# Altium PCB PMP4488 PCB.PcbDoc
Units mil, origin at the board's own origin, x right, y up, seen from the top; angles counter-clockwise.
Board outline 1702.94 x 773.81 mil, 2 copper layers (Top Layer, Bottom Layer), stack 62 mil thick; 34 components, 20 nets, 140 pads, 96 vias.
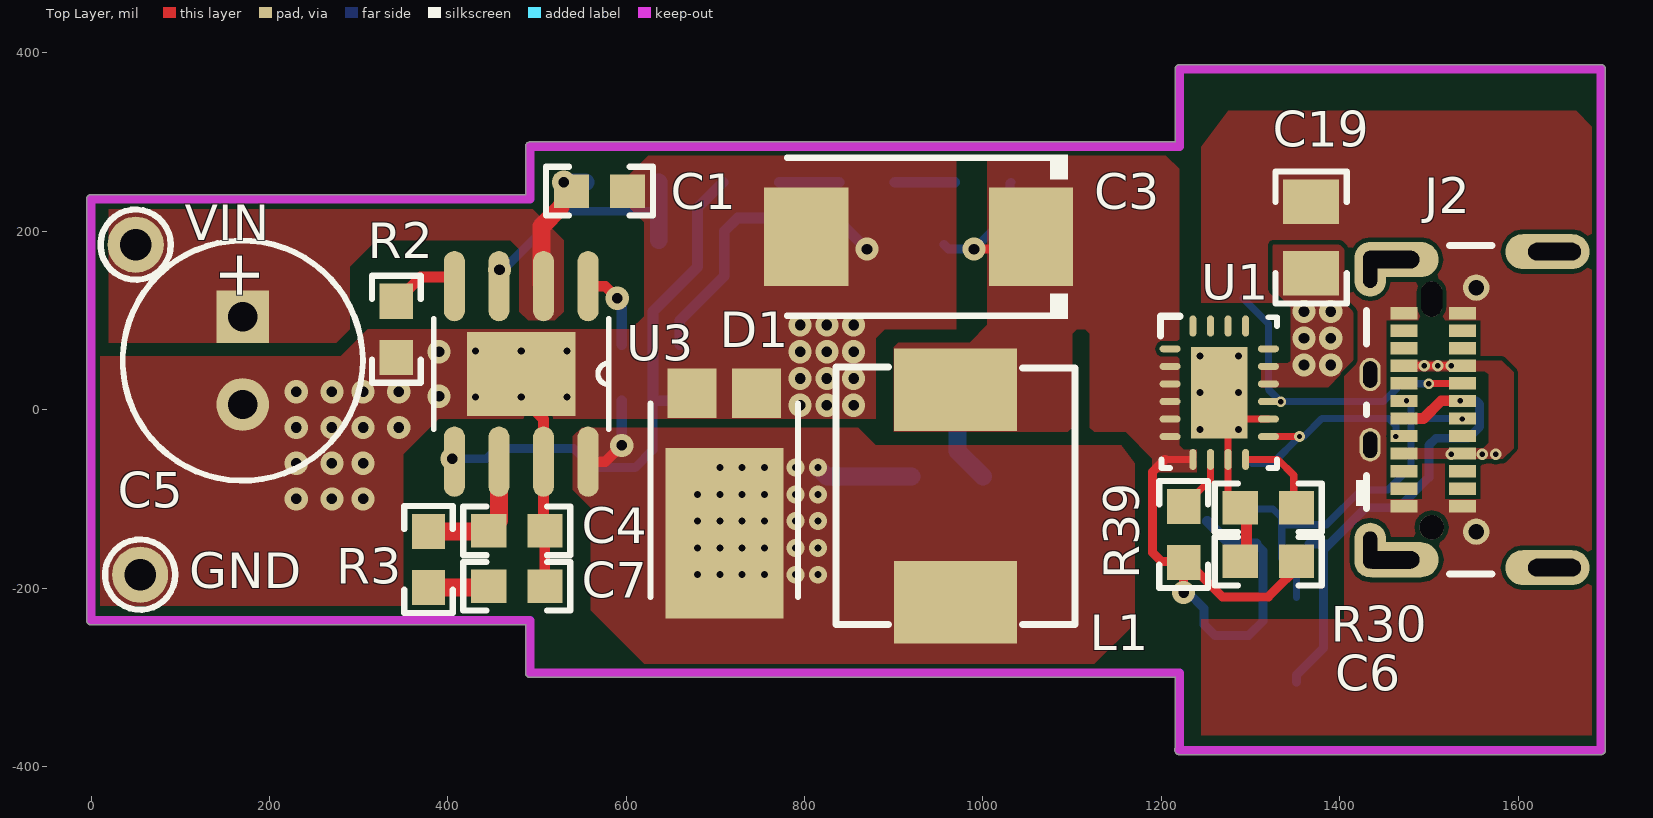
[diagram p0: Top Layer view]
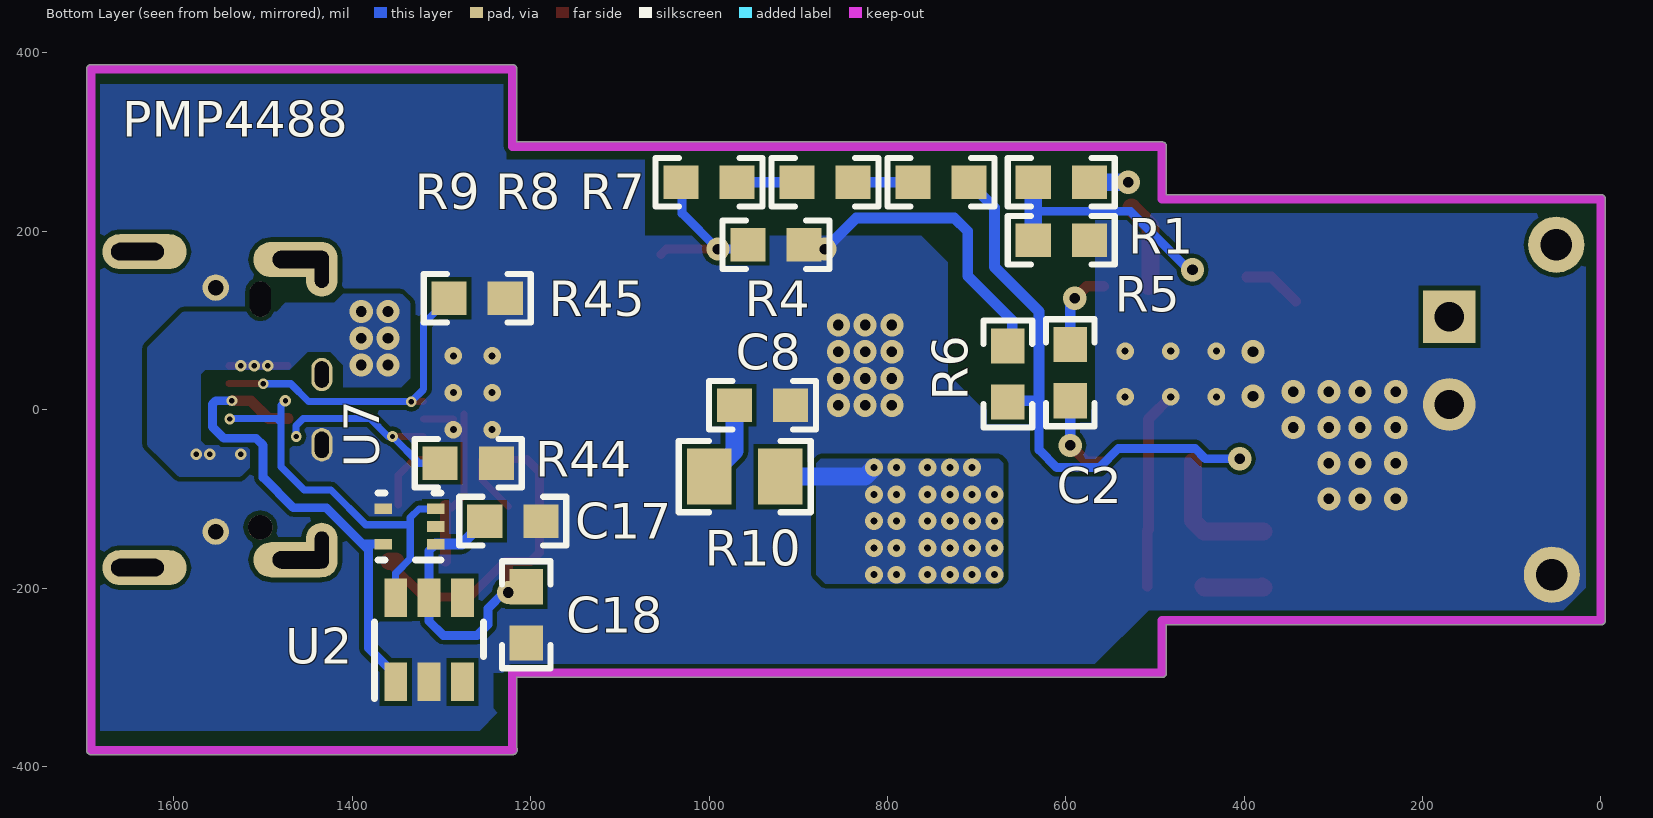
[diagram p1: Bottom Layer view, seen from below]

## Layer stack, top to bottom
Top Layer: signal copper 1.4
Dielectric: core 59.2, FR-4, Dk 4.8
Bottom Layer: signal copper 1.4

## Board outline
487.11,-295.28 487.11,-241.24 0,-241.24 cw(c0,-236.22) -5.01,-236.22 -5.01,236.22 cw(c0,236.22) 0,241.24 487.11,241.24 487.11,295.28 cw(c492.13,295.28) 492.13,300.29 1215.46,300.29 1215.46,381.89 cw(c1220.47,381.89) 1220.47,386.9 1692.91,386.9 cw(c1692.91,381.89) 1697.93,381.89 1697.93,-381.89 cw(c1692.91,-381.89) 1692.91,-386.9 1220.47,-386.9 cw(c1220.47,-381.89) 1216.91,-385.42 1216.93,-385.44 1216.45,-384.96 cw(c1220,-381.42) 1215.46,-379.29 1215.46,-300.29 492.13,-300.29 cw(c492.13,-295.28)

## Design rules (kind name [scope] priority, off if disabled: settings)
AcuteAngle [All] p1: minimum=4.50000000000000E+0001 checktracksonly=FALSE
AssemblyTestPointUsage [All] p1: valid=2
Clearance Clearance_Keepouts [All] p1: gap=5
Clearance Clearance_BoardEdge_MountingHoles [OnCopper and InComponentClass('Mounting Holes') vs IsKeepOut] p2: gap=40
Clearance Clearance_BoardEdge_Poly [OnCopper and InPoly vs IsKeepOut] p3: gap=25
Clearance Clearance_BoardEdge [OnCopper and Not InComponentClass('Logo') and not InComponentClass('FiducialMark') and not InRegion(1000,500,4000,800) and Not IsKeepout vs IsKeepOut] p4: gap=0
Clearance Clearance_Poly [InPolygon] p5: gap=6
Clearance [All] p6: gap=6
ComponentClearance ComponentClearance_MountingHoles_FiducialMarks [InComponentClass('Mounting Holes') vs InComponentClass('FiducialMark')] p1: gap=50 collisioncheckmode=3 verticalgap=10 showdistances=FALSE
ComponentClearance ComponentClearance_Shunt [InComponentClass('Header') vs InComponentClass('Shunt')] p2: gap=0 collisioncheckmode=3 verticalgap=0 showdistances=FALSE
ComponentClearance ComponentClearance_Logo [InComponentClass('Logo')] p3: gap=50 collisioncheckmode=3 verticalgap=10 showdistances=FALSE
ComponentClearance ComponentClearance_ScrewToNut [(HasFootprint('NY PMS 440 0025 PH')) vs (HasFootprint('Keystone_1902C'))] p4: gap=5 collisioncheckmode=3 verticalgap=10 showdistances=FALSE
ComponentClearance ComponentClearance_MountingHoles [InComponentClass('Mounting Holes')] p5: gap=250 collisioncheckmode=3 verticalgap=100000 showdistances=FALSE
ComponentClearance ComponentClearance_SmallPassives [HasFootprint('0201*') or HasFootprint('0402*') or HasFootprint('0508') or HasFootprint('0603*') or HasFootprint('0612') or HasFootprint('0805*') or HasFootprint('0815*') or HasFootprint('0830*') or HasFootprint('1206*') or HasFootprint('1210*') or HasFootprint('1808*') or HasFootprint('1812*') or HasFootprint('1825*') or HasFootprint('2010*') or HasFootprint('2220*') or HasFootprint('2225*') or HasFootprint('2512*') or HasFootprint('2728*') or HasFootprint('3518*') vs HasFootprint('0201*') or HasFootprint('0402*') or HasFootprint('0508') or HasFootprint('0603*') or HasFootprint('0612') or HasFootprint('0805*') or HasFootprint('0815*') or HasFootprint('0830*') or HasFootprint('1206*') or HasFootprint('1210*') or HasFootprint('1808*') or HasFootprint('1812*') or HasFootprint('1825*') or HasFootprint('2010*') or HasFootprint('2220*') or HasFootprint('2225*') or HasFootprint('2512*') or HasFootprint('2728*') or HasFootprint('3518*')] p6: gap=0 collisioncheckmode=3 verticalgap=0 showdistances=FALSE
ComponentClearance ComponentClearance_THtoSMT [IsThruComponent vs IsSMTComponent] p7: gap=0 collisioncheckmode=3 verticalgap=0 showdistances=FALSE
ComponentClearance ComponentClearance_THtoTH [IsThruComponent vs IsThruComponent] p8: gap=0 collisioncheckmode=3 verticalgap=0 showdistances=FALSE
ComponentClearance [All] p9: gap=0 collisioncheckmode=3 verticalgap=0 showdistances=FALSE
DiffPairsRouting [All] p1: maxlimit=100 minlimit=10 mostfreqgap=10 maxuncoupledlength=1000
FabricationTestPointUsage TestPointUsage [All] p1: valid=2 allowmultiple=FALSE
FabricationTestpoint Testpoint [All] p1: side=3 testpointundercomponent=TRUE minsize=40 maxsize=100 preferedsize=60 minholesize=0 maxholesize=40 preferedholesize=32 testpointgrid=1 allowsidetop=TRUE allowsidebottom=TRUE usegrid=TRUE gridtolerance=0.01
FanoutControl Fanout_LCC [IsLCC] p1: bgadir=Out bgaviamode=Centered fanoutstyle=Auto fanoutdirection=Alternating viagrid=1 // Fanout_LCC (Default Rule)
FanoutControl Fanout_BGA [IsBGA] p2: bgadir=Out bgaviamode=Centered fanoutstyle=Auto fanoutdirection=Alternating viagrid=1 // Fanout_BGA (Default Rule)
FanoutControl Fanout_Default [All] p4: bgadir=Out bgaviamode=Centered fanoutstyle=Auto fanoutdirection=Alternating viagrid=1 // Fanout_Default (Default Rule)
FanoutControl Fanout_Small [(CompPinCount < 5)] p5: bgadir=Out bgaviamode=Centered fanoutstyle=Auto fanoutdirection=OutThenIn viagrid=1 // Fanout_Small (Default Rule)
HoleSize [All] p1: absolutevalues=TRUE maxlimit=251 minlimit=5 maxpercent=80.000 minpercent=20.000
HoleToHoleClearance [All] p1: gap=0 allowstackedmicrovias=TRUE
MinimumAnnularRing MinimumAnnularRing_ThermalPadVias [IsVia and InAnyComponent] p1: minimumring=5.91
MinimumAnnularRing [All] p2: minimumring=2
MinimumSolderMaskSliver MinimumSolderMaskSliver_Logo [InComponentClass('Logo') vs InComponentClass('Logo')] p1: minsoldermaskwidth=0.7
MinimumSolderMaskSliver [All] p2: minsoldermaskwidth=2
PlaneConnect [All] p1: planeconnectstyle=Relief reliefexpansion=10 reliefentries=4 reliefconductorwidth=10 reliefairgap=10
PolygonConnect [All] p1: connectstyle=Direct reliefconductorwidth=10 reliefentries=4 polygonreliefangle="90 Angle" airgapwidth=10
RoutingVias ThermalPadVias [IsVia and InAnyComponent] p1: holewidth=12 width=26 viastyle="Through Hole" minholewidth=7.87 minwidth=19.68 maxholewidth=20 maxwidth=50
RoutingVias [All] p2: holewidth=12 width=26 viastyle="Through Hole" minholewidth=5 minwidth=10 maxholewidth=40 maxwidth=65
SilkToSilkClearance SilkToSilkClearance_Pb-FreeLogo [(HasFootprint('Pb-Free_Overlay_Medium') OR HasFootprint('Pb-Free_Overlay_Small')) vs (HasFootprint('Pb-Free_Overlay_Medium') OR HasFootprint('Pb-Free_Overlay_Small'))] p1: silktosilkclearance=1
SilkToSilkClearance [All] p2: silktosilkclearance=0
SilkscreenOverComponentPads "Silk to Solder Mask Opening" [IsPad] p1: minsilkscreentomaskgap=0
SolderMaskExpansion [All] p1: expansion=0
Width [All] p1: maxlimit=100 minlimit=6 preferedwidth=10 checkconnectedcopper=TRUE
13 further rules are at their usual default settings.

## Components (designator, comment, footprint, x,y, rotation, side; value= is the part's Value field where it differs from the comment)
C1 "C0603C104K5RACTU" 0603 570,245 r0 top
C2 "C0603C104K5RACTU" 0603 595,41.5 r270 bottom
C3 "EEFCX0J181R" CAPAE_SP-Cap_Standard 928,194 r180 top
C4 "C0603C104K5RACTU" 0603 477.32,-135.93 r0 top
C5 "6SEPC470MW" SEPC_C9 170,55 r270 top
C6 "C1608X7R1E104K" 0603 1320,-170 r180 top
C7 "C0603C104K5RACTU" 0603 477.32,-197.93 r0 top
C8 "C0603C104K5RACTU" 0603 940,5 r0 bottom
C17 "06033C104JAT2A" 0603 1220,-125 r180 bottom
C18 "06033C104JAT2A" 0603 1205,-230 r270 bottom
C19 "C0805C106K8PACTU" 0805_HV 1368,193 r90 top
D1 "SBR8A60P5-13" PowerDI5 710,-60 r270 top
GND "Suggest using a net name here" KEYSTONE1502-2 55,-185 r0 top (schematic designator J3)
J2 "UT12113-11602-7H" Foxconn_UT12113-11602-7H 1698,0 r90 top
L1 "CDH74NP-100LC" CDH74 969.32,-96.93 r180 top
R1 "RC0603FR-0739KL" 0603 605,255 r180 bottom
R2 "RC0603FR-07470KL" 0603 342.32,90.07 r90 top
R3 "CRCW060318K0JNEA" 0603 378.32,-167.93 r90 top
R4 "CRCW0603100KJNEA" 0603 925,185 r0 bottom
R5 "RC0603FR-0710KL" 0603 605,190 r0 bottom
R6 "CRCW06031K21FKEA" 0603 665,40 r270 bottom
R7 "RC0603FR-078K25L" 0603 740,255 r0 bottom
R8 "RC0603JR-070RL" 0603 870,255 r0 bottom
R9 "RC0603FR-0749R9L" 0603 1000,255 r0 bottom
R10 "CRCW0805100RFKEA" 0805_HV 960,-75 r180 bottom
R30 "CRCW0603100KFKEA" 0603 1320,-110 r0 top
R39 "CRCW060310K0JNEA" 0603 1225,-140 r270 top
R44 "CRCW060310K0JNEA" 0603 1270,-60 r0 bottom
R45 "CRCW060310K0JNEA" 0603 1260,125 r0 bottom
U1 "TPS25810RVC" RVC0020A 1265,19 r0 top
U2 "TPS2514ADBV" DBV0006A_N 1314,-258 r90 bottom
U3 "TPS54340DDA" DDA0008E_N 482.32,40.07 r270 top
U7 "TPD2E001DRLRG4" DRL0005A 1336,-131 r0 bottom
VIN "Suggest using a net name here" KEYSTONE1502-2 50,185 r0 top (schematic designator J1)

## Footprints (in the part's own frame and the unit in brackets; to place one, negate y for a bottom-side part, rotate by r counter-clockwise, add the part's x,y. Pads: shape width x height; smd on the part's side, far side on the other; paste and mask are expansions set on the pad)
0603 [mm] "0603 from SM-752 data"
  rect 1x0.95 smd: 1(-0.8,0) 2(0.8,0)
  silkscreen extent -1.52,-0.69 1.52,0.69, body extent -0.87,-0.47 0.87,0.47, height 0.85
0805_HV [mil] "0805 with 30mil clearance between pads"
  rect 50x63 smd: 1(-40,0) 2(40,0)
  silkscreen extent -74,-40 74,40, body extent -43,-29 43,29, height 43
CAPAE_SP-Cap_Standard [mm] "Recommended land pattern for standard Panasonic SP-CAP capacitors"
  rect 2.4x2.8 smd: 1(-3.2,0) 2(3.2,0)
  silkscreen extent -4.25,-2.34 3.75,2.34, body extent -3.75,-2.25 3.75,2.25, height 2.11
CDH74 [mm] "SMD, 2-Leads, Body 7.3x8mm"
  rect 3.5x2.35 smd: 1(0,3.025) 2(0,-3.025)
  silkscreen extent -3.4,-3.68 3.4,3.65, body extent -3.65,-4 3.65,4, height 5.2
DBV0006A_N [mm] "SOT23, 6-Leads, Body 2.9x1.6mm, Pitch 0.95mm, Lead Span 2.8mm, IPC Medium Density"
  rect 1.1x0.65 smd: 1(-1.2,0.95) 2(-1.2,0) 3(-1.2,-0.95) 4(1.2,-0.95) 5(1.2,0) 6(1.2,0.95)
  silkscreen extent -1.68,-1.55 0.5,1.55, body extent -1.42,-1.46 1.42,1.46, height 1.11
DDA0008E_N [mm]
  oval 2x0.6 smd: 1(-2.5,1.905) 2(-2.5,0.635) 3(-2.5,-0.635) 4(-2.5,-1.905) 5(2.5,-1.905) 6(2.5,-0.635) 7(2.5,0.635) 8(2.5,1.905)
  rect 2.4x3.1 smd: 9(0,0)
  silkscreen extent -1.58,-2.49 1.58,2.49, body extent -2.98,-2.45 2.98,2.45, height 1.5
DRL0005A [mm] "SOTFL, 5-Flat Leads, Body 1.2x1.6x0.6mm, Pitch 0.5mm, TI recommended"
  rect 0.5x0.3 smd: 1(-0.75,0.5) 2(-0.75,0) 3(-0.75,-0.5) 4(0.75,-0.5) 5(0.75,0.5)
  silkscreen extent -0.9,-0.95 0.9,0.95, body extent -0.85,-0.85 0.85,0.85, height 0.62
Foxconn_UT12113-11602-7H [mm] "Connector, Receptacle, USB TYPE C, R/A, SMT"
  rect 0.35x0.77 smd: A1(-2.75,5.735) A2(-2.25,5.735) A3(-1.75,5.735) A4(-1.25,5.735) A5(-0.75,5.735) A6(-0.25,5.735) A7(0.25,5.735) A8(0.75,5.735) A9(1.25,5.735) A10(1.75,5.735) A11(2.25,5.735) A12(2.75,5.735) B1(2.75,4.065) B2(2.25,4.065) B3(1.75,4.065) B4(1.25,4.065) B5(0.75,4.065) B6(0.25,4.065) B7(-0.25,4.065) B8(-0.75,4.065) B9(-1.25,4.065) B10(-1.75,4.065) B11(-2.25,4.065) B12(-2.75,4.065)
  round 0.7 hole 0.7 unplated mask+0: ALIGN1(-3.35,4.95)
  rrect100% 1x0.6 hole 0.6 slot 1 at 0 deg unplated mask+0: ALIGN2(3.15,4.95)
  rrect100% 0.5x1.6 hole 0.5 slot 1.6 at 90 deg mask+0: S1(-4.275,6.1) S4(4.275,6.1)
  rrect100% 0.95x0.6 hole 0.4 slot 0.75 at 0 deg: S2(-1,6.7) S3(1,6.7)
  round 0.75 hole 0.45: S5(-3.475,3.68) S6(3.475,3.68)
  rrect100% 0.5x1.5 hole 0.5 slot 1.5 at 90 deg mask+0: S7(-4.5,1.45) S8(4.5,1.45)
  rrect100% 1x2.4 all layers, no hole: ""(-4.5,1.65) ""(-4.275,5.95) ""(4.275,5.95) ""(4.5,1.65)
  rrect100% 1.555x0.9 all layers, no hole: ""(-3.998,6.7) ""(3.998,6.7)
  rrect100% 1.055x0.4 hole 0.4 slot 1.055 at 0 deg mask+0: ""(-3.998,6.7) ""(3.998,6.7)
  silkscreen extent -4.67,3.23 4.67,7.1, body extent -4.68,-2.3 4.68,6.8, height 3.37
KEYSTONE1502-2 [mm] "Double Turret"
  round 1.6 hole 0.9: 1(0,0)
  silkscreen extent -1,-1 1,1
PowerDI5 [mm] "Diodes Inc recommended land pattern, ap02001.pdf rev 60"
  rect 1.4x1.39 smd: 1(-1.991,0.92) 2(-1.991,-0.92)
  rect 4.86x3.36 smd: 3(1.991,0)
  silkscreen extent -1.7,-2.1 3.8,2.1, body extent -2.27,-2.03 4.33,2.03, height 1.17
RVC0020A [mm] "TI"
  oval 0.6x0.2 smd: 1(-1.4,1.25) 2(-1.4,0.75) 3(-1.4,0.25) 4(-1.4,-0.25) 5(-1.4,-0.75) 6(-1.4,-1.25) 11(1.4,-1.25) 12(1.4,-0.75) 13(1.4,-0.25) 14(1.4,0.25) 15(1.4,0.75) 16(1.4,1.25)
  oval 0.2x0.6 smd: 7(-0.75,-1.9) 8(-0.25,-1.9) 9(0.25,-1.9) 10(0.75,-1.9) 17(0.75,1.9) 18(0.25,1.9) 19(-0.25,1.9) 20(-0.75,1.9)
  rect 1.6x2.6 smd paste-1: 21(0,0)
  silkscreen extent -1.68,-2.15 1.65,2.18, body extent -1.55,-2.05 1.55,2.05, height 0.8
SEPC_C9 [mm] "PANASONIC"
  rect 1.5x1.5 hole 0.838: 1(-1.25,0)
  round 1.5 hole 0.838: 2(1.25,0)
  silkscreen extent -3.42,-3.42 3.42,3.42, body extent -3.41,-3.41 3.41,3.41, height 9.05

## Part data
C1 C2 C4 C7 C8: "CAP, CERM, 0.1 μF, 50 V, +/- 10%, X7R, 0603"
C3: "CAP, AL, 180 μF, 6.3 V, +/- 20%, 15 ohm, SMD"
C5: "CAP, AL, 470 μF, 6.3 V, +/- 20%, 0.007 ohm, TH"
C6: "CAP, CERM, 0.1 μF, 25 V, +/- 10%, X7R, 0603"
C17 C18: "CAP, CERM, 0.1 μF, 25 V, +/- 5%, X7R, 0603"
C19: "CAP, CERM, 10 μF, 10 V, +/- 10%, X5R, 0805"
D1: "Diode, Super Barrier Rectifier, 60 V, 8 A, PowerDI5"
GND VIN: library part 1502-2, "Terminal, Turret, TH, Double"
J2: "Connector, Receptacle, USB TYPE C, R/A, SMT"
L1: "Inductor, Wirewound, Ferrite, 10 μH, 2.75 A, 0.043 ohm, SMD"
R1: "RES, 39.0 k, 1%, 0.1 W, 0603"
R2: "RES, 470 k, 1%, 0.1 W, 0603"
R3: "RES, 18 k, 5%, 0.1 W, 0603"
R4: "RES, 100 k, 5%, 0.1 W, 0603"
R5: "RES, 10.0 k, 1%, 0.1 W, 0603"
R6: "RES, 1.21 k, 1%, 0.1 W, 0603"
R7: "RES, 8.25 k, 1%, 0.1 W, 0603"
R8: "RES, 0, 5%, 0.1 W, 0603"
R9: "RES, 49.9, 1%, 0.1 W, 0603"
R10: "RES, 100 ohm, 1%, 0.125W, 0805"
R30: "RES, 100 k, 1%, 0.1 W, 0603"
R39 R44 R45: "RES, 10 k, 5%, 0.1 W, 0603"
U1: "USB Type-C DFP Controller and Power Switch with Load Detection, RVC0020A"
U2: "USB Dedicated Charging Port Controller, DBV0006A"
U3: "42 V Input, 3.5 A, Step Down DC-DC Converter with Eco-mode, DDA0008E"
U7: "Low-Capacitance + / - 15 kV ESD-Protection Array for High-Speed Data Interfaces, 2 Channels, -40 to +85 degC, 5-pin SOT (DRL), Green (RoHS & no Sb/Br)"

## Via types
v1: diameter 26, hole 12, Top Layer to Bottom Layer, 42 vias
v2: diameter 20, hole 8, Top Layer to Bottom Layer, 29 vias
v3: diameter 13, hole 6, Top Layer to Bottom Layer, 7 vias
v4: diameter 19.68, hole 7.87, Top Layer to Bottom Layer, tented top, 6 vias
v5: diameter 12, hole 6, Top Layer to Bottom Layer, 6 vias
v6: diameter 19.68, hole 7.87, Top Layer to Bottom Layer, 6 vias

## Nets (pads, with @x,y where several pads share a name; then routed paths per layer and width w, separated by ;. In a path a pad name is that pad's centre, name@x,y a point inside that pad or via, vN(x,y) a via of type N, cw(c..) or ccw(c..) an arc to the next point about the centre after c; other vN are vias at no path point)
5V: C19.1 J2.A4 J2.A9 J2.B4 J2.B9 U1.14 U1.15 | length 65.7
  Top Layer w8: J2.A9 J2.B4
  other v1: 1360,50 1390,50 1360,80 1390,80 1360,110 1390,110
  other v3: 1525,-50 1560,-50 1575,-50 1495,49.21 1510,49.21 1525,49.21
CC1: J2.A5 R44.2 U1.11 | length 232.5
  Top Layer w8: U1.11 1354.79,-30.21 v5(1355,-30)
  Bottom Layer w8: R44.2 1325,-60 v5(1355,-30) 1360,-30 1380,-10 1455,-10 1463,-18 v5(1463,-30)
CC2: J2.B5 R45.2 U1.13 | length 360
  Top Layer w8: U1.13 1333.84,9.16 v5(1334,9) ; v5(1500,29) 1500.53,29.53 J2.B5
  Bottom Layer w8: R45.2 1320,96.5 1320,23 v5(1334,9) 1449,9 1469,29 v5(1500,29)
D+: J2.A6 J2.B6 U2.1 U7.5 | length 556.6
  Top Layer w12: J2.A6 1493.91,-9.84 1513.76,10 v5(1535,10)
  Bottom Layer w10: U2.1 1351.4,-297.6 1382,-267 1382,-157 1388.31,-150.69 ; U7.5 1388.31,-150.69 ; v5(1535,10) 1553,10 1557,6 1557,-19 1544,-32 1508,-32 1500,-40 1500,-76 1466,-110 1429,-110 1388.31,-150.69
D-: J2.A7 J2.B7 U2.6 U7.3 | length 436.7
  Bottom Layer w8: U7.3 1325.32,-111.32 1335,-121 1335,-129 ; U2.6 1351.4,-183.4 1335,-167 1335,-129 ; v3(1475,10) 1480,5 1480,-15 ; v5(1537.43,-10.37) 1537.06,-10 1485,-10 1480,-15 ; 1335,-129 1385,-129 1424,-90 1454,-90 1480,-64 1480,-15
GND: C1.2 C3.2 C4.2 C5.2 C6.2 C7.2 C8.1 C17.2 C18.2 C19.2 D1.1 D1.2 GND.1 J2.A1 J2.A12 J2.B1 J2.B12 J2.S2 J2.S3 J2.S5 J2.S6 R2.1 R4.1 R5.1 R6.1 R30.1 R44.1 R45.1 U1.9 U1.12 U1.21 U2.2 U3.7 U3.9 U7.4 | length 761.8
  Top Layer w8: U1.21@1274.84,-5 U1.9 1274.84,-96.34 R30.1 ; U1.21@1286.65,-10.53 U1.12 ; R30.1@1293.5,-105 R30.1@1295.5,-107
  Top Layer w12: v4(482.32,14.48) 507.32,-10.52 U3.7 507.32,-134.43 C4.2 C7.2 ; C6.2@1295.5,-170 R30.1@1295.5,-107
  Bottom Layer w12: R6.1@660,72.99 660,100 710,150 710,200 725,215 835,215 v1(870,180)
  other v1: 230,-100 270,-100 305,-100 230,-60 270,-60 305,-60 230,-20 270,-20 305,-20 345,-20 795,5 825,5 855,5 390,15 230,20 270,20 305,20 345,20 795,35 825,35 855,35 390,65 795,65 825,65 855,65 795,95 825,95 855,95
  other v4: 431.14,14.48 533.5,14.48 431.14,65.66 482.32,65.66 533.5,65.66
  other v6: 1243.35,-22.34 1286.65,-22.34 1243.35,19 1286.65,19 1243.35,60.34 1286.65,60.34
NetC1_1: C1.1 C5.1 R1.2 U3.2 VIN.1 | length 122.9
  Top Layer w20: U3.2 505,140.82 505,205.5 C1.1@526.5,227
  Bottom Layer w20: v1(530,255) R1.2@554.5,255
NetC2_1: C2.1 U3.1 | length 92.3
  Top Layer w12: U3.1 576.5,138.5 v1(590,125)
  Bottom Layer w12: v1(590,125) 595,120 C2.1
NetC2_2: C2.2 D1.3 L1.1 R10.2 U3.8 | length 204.4
  Top Layer w12: U3.8 576.65,-58.35 v1(595,-40)
  Bottom Layer w12: v1(595,-40) C2.2
  Bottom Layer w20: v2(815,-65) 825,-75 R10.2
  other v2: 680,-185 705,-185 730,-185 755,-185 790,-185 815,-185 680,-155 705,-155 730,-155 755,-155 790,-155 815,-155 680,-125 705,-125 730,-125 755,-125 790,-125 815,-125 680,-95 705,-95 730,-95 755,-95 790,-95 815,-95 705,-65 730,-65 755,-65 790,-65
NetC3_1: C3.1 C6.1 C17.1 C18.1 L1.2 R4.2 R9.2 R39.2 U1.2 U1.3 U1.4 U1.5 U1.6 U1.7 U2.5 U7.1 | length 866.8
  Top Layer w8: 1204.2,-55.8 U1.7
  Top Layer w10: v1(990,180) 1047.98,180 C3.1@1053.98,174 ; 1204.2,-55.8 1190,-70 1190,-160 1200,-170 R39.2@1228.5,-170 ; v1(1225,-205) 1225,-173.5 R39.2@1228.5,-170 ; C6.1@1358.5,-170 1358.5,-171.5 1320,-210 1268.5,-210 R39.2@1228.5,-170
  Top Layer w20: C6.1 C6.1@1358.5,-170
  Bottom Layer w10: R4.2 961.5,180 v1(990,180) 1030.2,220.2 1030.2,253.7 R9.2 ; v1(1225,-205) 1230,-205 1248,-223 1248,-241 1260,-253 1298,-253 1314,-237 U2.5 1314,-158.21 U7.1
  Bottom Layer w12: C17.1 1277.18,-150.69 U7.1
NetC4_1: C4.1 R3.2 U3.6 | length 150
  Top Layer w20: R3.2 445.32,-136.43 C4.1 457.32,-124.43 U3.6
NetC7_1: C7.1 R3.1 | length 70.2
  Top Layer w20: R3.1@379.82,-197.93 R3.1 444.33,-199.43 C7.1
NetC8_2: C8.2 R10.1 | length 91.8
  Bottom Layer w20: C8.2 971.5,-46.5 R10.1
NetR1_1: R1.1 R5.2 U3.3 | length 270.6
  Bottom Layer w10: v1(458,157) 462,157 527.5,222.5 636.5,222.5
  Bottom Layer w20: R5.2 636.5,222.5 R1.1
NetR2_2: R2.2 U3.4 | length 66
  Top Layer w12: R2.2 369.52,148.77 U3.4@397.05,148.77
NetR6_2: R6.2 R7.1 U3.5 | length 609.5
  Bottom Layer w10: v1(405,-55) 443.5,-55 455,-43.5 541,-43.5 562.5,-65 610,-65 630,-45 630,10
  Bottom Layer w12: R6.2@660,10 630,10 630,110 680,160 680,226.5 R7.1
NetR7_2: R7.2 R8.1 | length 67
  Bottom Layer w12: R7.2 R8.1
NetR8_2: R8.2 R9.1 | length 67
  Bottom Layer w12: R8.2 R9.1
NetR30_2: R30.2 U1.10 | length 94.8
  Top Layer w8: U1.10 1330.8,-55.8 1348.5,-73.5 R30.2@1348.5,-107
NetR39_1: R39.1 U1.8 | length 65.2
  Top Layer w8: R39.1 1255.16,-78.35 U1.8
pads on no net: J2. J2.A2 J2.A3 J2.A8 J2.A10 J2.A11 J2.ALIGN1 J2.ALIGN2 J2.B2 J2.B3 J2.B8 J2.B10 J2.B11 J2.S1 J2.S4 J2.S7 J2.S8 U1.1 U1.16 U1.17 U1.18 U1.19 U1.20 U2.3 U2.4 U7.2

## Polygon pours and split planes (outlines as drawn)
5V on Top Layer "Top Layer-No Net 4" (solid, pour order 12): 1312,52 1342,52 1345,55 1345,115 1325,135 1325,185 1400,185 1405,180 1405,120 1415,110 1415,55 1387,25 1312,25
NetC1_1 on Top Layer "Top Layer-No Net" (solid, pour order 2): 495,225 530,190 530,110 520,100 490,100 480,110 480,180 470,190 320,190 290,160 290,90 275,75 20,75 20,225
GND on Top Layer "Top Layer-No Net 1" (solid, pour order 4): 10,60 280,60 310,90 605,90 620,105 620,210 600,230 600,260 625,285 970,285 970,90 890,90 880,80 880,-10 390,-10 350,-50 350,-220 10,-220
NetC2_2 on Top Layer "Top Layer-No Net 2" (solid, pour order 6): 540,-30 550,-20 860,-20 880,-40 1155,-40 1170,-60 1170,-240 1125,-285 620,-285 560,-225 560,-110 540,-90
NetC3_1 on Top Layer "Top Layer-No Net 6" (solid, pour order 20): 1005,285 1205,285 1220,270 1220,-40 1225,-45 1240,-45 1240,-70 1190,-70 1190,-55 1160,-25 1125,-25 1120,-20 1120,85 1115,90 1105,90 1100,85 1100,-20 1095,-25 900,-25 900,70 905,75 985,75 1005,95
GND on Top Layer "Top Layer-No Net 5" (solid, pour order 18): 1275,335 1665,335 1685,315 1685,-365 1245,-365 1245,-235 1405,-235 1405,120 1245,120 1245,295
5V on Top Layer "Top Layer-No Net 3" (solid, pour order 8): 1460,55 1582,55 1595,42 1595,-43 1583,-55 1460,-55 1460,-43 1461,-42 1462,-43 1561,-43 1567,-37 1567,40 1562,43 1458,43 1458,54 1459,55 1460,55 1461,54 1460,54
GND on Bottom Layer "Bottom Layer-No Net 1" (solid, remove dead copper, pour order 16): 17.22,220.08 567.22,220.08 567.22,0.08 692.22,0.08 732.22,40.08 732.22,165.08 762.22,195.08 1072.22,195.08 1072.22,280.08 1227.22,280.08 1227.22,365.08 1687.22,365.08 1687.22,-359.92 1257.22,-359.92 1237.22,-339.92 1242.22,-334.92 1242.22,-294.92 577.22,-294.92 507.22,-224.92 42.22,-224.92 17.22,-199.92
NetC2_2 on Bottom Layer "Bottom Layer-No Net 2" (solid, pour order 22): 670,-65 670,-60 675,-55 790,-55 875,-55 880,-60 880,-185 870,-195 675,-195 670,-190 670,-60
5V on Bottom Layer "Bottom Layer-No Net" (solid, pour order 14): 1335,35 1335,120 1345,130 1410,130 1420,120 1475,120 1485,110 1590,110 1630,70 1630,-40 1595,-75 1525,-75 1515,-65 1515,-45 1520,-40 1565,-40 1570,-35 1570,40 1565,45 1470,45 1450,65 1425,65 1410,50 1410,25 1345,25

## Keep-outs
Keep-Out Layer:
  lines w10: 1220,-381.42 1220.47,-381.89 ; 1220.47,-381.89 1692.91,-381.89 1692.91,381.89 1220.47,381.89 1220.47,295.28 492.13,295.28 492.13,236.22 0,236.22 0,-236.22 492.13,-236.22 492.13,-295.28 1220.47,-295.28 1220.47,-381.89
  text ".Layer_Name" at 629.5,-1589.97 h60

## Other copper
Top Layer:
  text ".Layer_Name" at 629.5,-1589.97 h60
Bottom Layer:
  text ".Layer_Name" at 629.5,-1589.97 h60

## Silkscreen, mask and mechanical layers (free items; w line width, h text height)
Top Overlay:
  text ".Layer_Name" at 629.5,-1589.97 h60
Bottom Overlay:
  text "PMP4488" at 1658,306 h40
  text ".Layer_Name" at 629.5,-1589.97 h60
Top Paste:
  text ".Layer_Name" at 629.5,-1589.97 h60
Bottom Paste:
  text ".Layer_Name" at 629.5,-1589.97 h60
Top Solder:
  region: 640,267.5 735,267.5 745,257.5 745,72.5 740,62.5 655,62.5 635,82.5 635,257.5
  region: 105,-110 120,-95 315,-95 340,-120 340,-205 335,-210 125,-210 105,-190
  text ".Layer_Name" at 629.5,-1589.97 h60
  text ".Layer_Name" at 629.5,-1589.97 h60
Bottom Solder:
  region: 215,-85 515,-85 530,-100 530,-185 210,-185 200,-175 200,-100
  region: 235,95 535,95 550,80 550,-5 230,-5 220,5 220,80
  region: 875,-55 675,-55 670,-60 670,-190 675,-195 870,-195 880,-185 880,-60
  text ".Layer_Name" at 629.5,-1589.97 h60
Drill Guide:
  text ".Layer_Name" at 629.5,-1589.97 h60
M1 Board Outline:
  text ".Layer_Name" at 629.5,-1589.97 h60
M2 Board Dimensions:
  rectangle: 52.5,-1006.48 177.5,-881.48
  rectangle: 177.5,-1131.48 552.5,-1006.48
  lines w7: 52.5,-1006.48 1052.5,-1006.48 ; 52.5,-881.48 52.5,-1131.48 1052.5,-1131.48 1052.5,-881.48 ; 177.5,-1131.48 177.5,-881.48 ; 302.5,-1131.48 302.5,-881.48 ; 552.5,-1131.48 552.5,-881.48 ; 802.5,-1131.48 802.5,-881.48
  text ".Layer_Name" at 629.5,-1589.97 h60
M3 3D STEP Top:
  text ".Layer_Name" at 629.5,-1589.97 h60
M4 3D STEP Bottom:
  text ".Layer_Name" at 629.5,-1589.97 h60
M5 Assembly Top:
  lines w10: -239.5,-1661.64 6360.5,-1661.64 ; -239.5,-1458.31 6362.5,-1458.31 ; -239.5,-1254.98 -239.5,-1864.98 3765.5,-1864.98 6362.5,-1864.98 6362.5,-1254.98 -239,-1254.98 -239,-1864.98 1336.5,-1864.98 ; 2225.5,-1864.98 2225.5,-1254.98 ; 3492.5,-1458.31 3492.5,-1254.98 ; 4332.5,-1458.31 4332.5,-1254.98 ; 4954.5,-1871.48 4954.5,-1668.64
  text "COMPONENTS MARKED 'DNP' SHOULD NOT BE POPULATED." at 1206,-1049.98 h60
  text "ASSEMBLY VARIANT:" at 1205.5,-1165.48 h60
  text ".VariantName" at 2241.5,-1165.48 h60
  text "PCB VIEWED FROM TOP SIDE" at -176,-1387.14 h60
  text "BOARD #:" at 2300.5,-1387.14 h60
  text ".PRJ_Number" at 2846,-1387.14 h60
  text "REV:" at 3690.5,-1387.14 h60
  text ".PCB_Rev" at 3982,-1387.14 h60
  text "SVN REV:" at 4528.5,-1387.14 h60
  text ".VersionControl_RevNumber" at 5034.5,-1387.14 h60
  text "PLOT NAME =" at -176,-1795.81 h60
  text ".plot_File_Name" at 629.5,-1795.81 h60
  text "GENERATED    :" at 2302.5,-1795.81 h60
  text ".Print_Date" at 3172,-1795.81 h60
  text ".Print_Time" at 3901,-1795.81 h60
  text "TEXAS INSTRUMENTS" at 5165.5,-1795.81 h60
M6 Assembly Bottom:
  lines w10: -240,-1458.81 6362,-1458.81 ; -238,-1662.14 6362,-1662.14 ; 1168,-1871.98 1168,-1669.14 ; 1790,-1458.81 1790,-1255.48 ; 2630,-1458.81 2630,-1255.48 ; 3897,-1865.48 3897,-1255.48 ; 4786,-1865.48 6361.5,-1865.48 6361.5,-1255.48 -240,-1255.48 -240,-1865.48 2357,-1865.48 6362,-1865.48 6362,-1255.48
  text "COMPONENTS MARKED 'DNP' SHOULD NOT BE POPULATED." at 6154.5,-1049.48 h60
  text ".VariantName" at 5110.5,-1165.48 h60
  text "ASSEMBLY VARIANT:" at 6149.5,-1165.48 h60
  text ".VersionControl_RevNumber" at 1088,-1387.64 h60
  text "SVN REV:" at 1594,-1387.64 h60
  text ".PCB_Rev" at 2140.5,-1387.64 h60
  text "REV:" at 2432,-1387.64 h60
  text ".PRJ_Number" at 3276.5,-1387.64 h60
  text "BOARD #:" at 3822,-1387.64 h60
  text "PCB VIEWED FROM BOTTOM SIDE" at 6298.5,-1387.64 h60
  text "TEXAS INSTRUMENTS" at 957,-1796.31 h60
  text ".Print_Time" at 2221.5,-1796.31 h60
  text ".Print_Date" at 2950.5,-1796.31 h60
  text "GENERATED    :" at 3820,-1796.31 h60
  text ".plot_File_Name" at 5493,-1796.31 h60
  text "PLOT NAME =" at 6298.5,-1796.31 h60
M9 Title Sheet:
  drawing of 57 lines, arcs and shapes, not listed
  text "1" at 739.84,7336.5 h70
  text "2" at 3235.5,7336.5 h70
  text "3" at 5724.84,7336.5 h70
  text "4" at 8231.51,7336.5 h70
  text "5" at 10730.5,7336.5 h70
  text "6" at 13235.5,7336.5 h70
  text "A" at -416.5,6193.5 h70
  text "A" at 14383.5,6193.5 h70
  text "B" at -416.5,3813.5 h70
  text "B" at 14383.5,3813.5 h70
  text "C" at -416.5,1438.5 h70
  text "C" at 14383.5,1438.5 h70
  text "PROJECT TITLE:" at 11343.5,-422.5 h45
  text ".PRJ_Title" at 11393.5,-555.83 h70
  text "DESIGNED FOR:" at 11343.5,-723.5 h45
  text ".PRJ_Customer" at 11393.5,-863.5 h70
  text "D" at -416.5,-931.5 h70
  text "D" at 14383.5,-931.5 h70
  text "FILE NAME:" at 11343.5,-1023.5 h45
  text ".PCB_File_Name_No_Path" at 11393.5,-1143.5 h70
  text "Texas Instruments (TI) and/or its licensors do not warrant the accuracy or completeness of this specification" at 6374,-1305.34 h45
  text "ENGINEER:" at 11343.5,-1313.5 h45
  text "LAYOUT BY:" at 12848.5,-1313.5 h45
  text "or any information contained therein. TI and/or its licensors do not warrant that this design will meet" at 6329.01,-1418 h45
  text ".PRJ_Engineer" at 11393.5,-1468.49 h70
  text ".PCB_Layout" at 12899,-1468.49 h70
  text "the specifications, will be suitable for your application or fit for any particular purpose, or will operate in" at 6329.01,-1530.67 h45
  text ".Layer_Name" at 577,-1558.49 h60
  text "ALTIUM DESIGNER VERSION:" at 12848.5,-1623.5 h45
  text "an implementation. TI and/or its licensors do not warrant that the design is production worthy. You should" at 6329.01,-1643.33 h45
  text "completely validate and test your design implementation to confirm the system functionality for your application." at 6374,-1756 h45
  text ".print_Scale" at 11393.5,-1756.83 h70
  text ".Application_BuildNumber" at 12899,-1756.83 h70
  text "1" at 739.84,-1963.5 h70
  text "2" at 3235.5,-1963.5 h70
  text "3" at 5724.84,-1963.5 h70
  text "4" at 8231.51,-1963.5 h70
  text "5" at 10730.5,-1963.5 h70
  text "6" at 13235.5,-1963.5 h70
M10 Fab Notes:
  text ".Layer_Name" at 629.5,-1589.97 h60
M11 Gerber Information:
  lines w10: -239.5,-1661.64 6360.5,-1661.64 ; -239.5,-1458.31 6362.5,-1458.31 ; -239.5,-1254.98 -239.5,-1864.98 3765.5,-1864.98 6362.5,-1864.98 6362.5,-1254.98 -239,-1254.98 -239,-1864.98 1336.5,-1864.98 ; 2225.5,-1864.98 2225.5,-1254.98 ; 3492.5,-1458.31 3492.5,-1254.98 ; 4332.5,-1458.31 4332.5,-1254.98 ; 4954.5,-1871.48 4954.5,-1668.64
  text "ALL ARTWORK VIEWED FROM TOP SIDE" at -176,-1387.14 h60
  text "BOARD #:" at 2300.5,-1387.14 h60
  text ".PRJ_Number" at 2846,-1387.14 h60
  text "REV:" at 3690.5,-1387.14 h60
  text ".PCB_Rev" at 3982,-1387.14 h60
  text "SVN REV:" at 4528.5,-1387.14 h60
  text ".VersionControl_RevNumber" at 5034.5,-1387.14 h60
  text "LAYER NAME =" at -176,-1589.97 h60
  text "PLOT NAME =" at -176,-1795.81 h60
  text ".plot_File_Name" at 629.5,-1795.81 h60
  text "GENERATED    :" at 2302.5,-1795.81 h60
  text ".Print_Date" at 3172,-1795.81 h60
  text ".Print_Time" at 3901,-1795.81 h60
  text "TEXAS INSTRUMENTS" at 5165.5,-1795.81 h60
M12 Stackup:
  text ".Layer_Name" at 629.5,-1589.97 h60
M13 Component Bodies Top:
  text ".Layer_Name" at 629.5,-1589.97 h60
M14 Component Bodies Bottom:
  text ".Layer_Name" at 629.5,-1589.97 h60
M15 Courtyards Top:
  text ".Layer_Name" at 629.5,-1589.97 h60
M16 Courtyards Bottom:
  text ".Layer_Name" at 629.5,-1589.97 h60
Drill Drawing:
  text ".Layer_Name" at 629.5,-1589.97 h60

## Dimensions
52.5,-1131.48 to 1052.5,-1131.48 on M2 Board Dimensions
